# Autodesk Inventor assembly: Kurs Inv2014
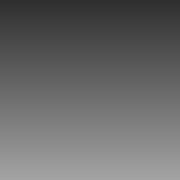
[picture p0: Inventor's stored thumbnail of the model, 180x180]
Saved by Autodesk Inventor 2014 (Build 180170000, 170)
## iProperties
Created: 2010-03
Part Number: Kurs Inv2014
Document SubType Name: Assembly
Designer: Johan Wedeen
Manufacturer: Standard
Standards Organization: Custom
Author: Johan Wedeen
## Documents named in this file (1)
- Z:\Kompendier\Inventor2014\kurs inv204\Kurs Inv2014.iam
